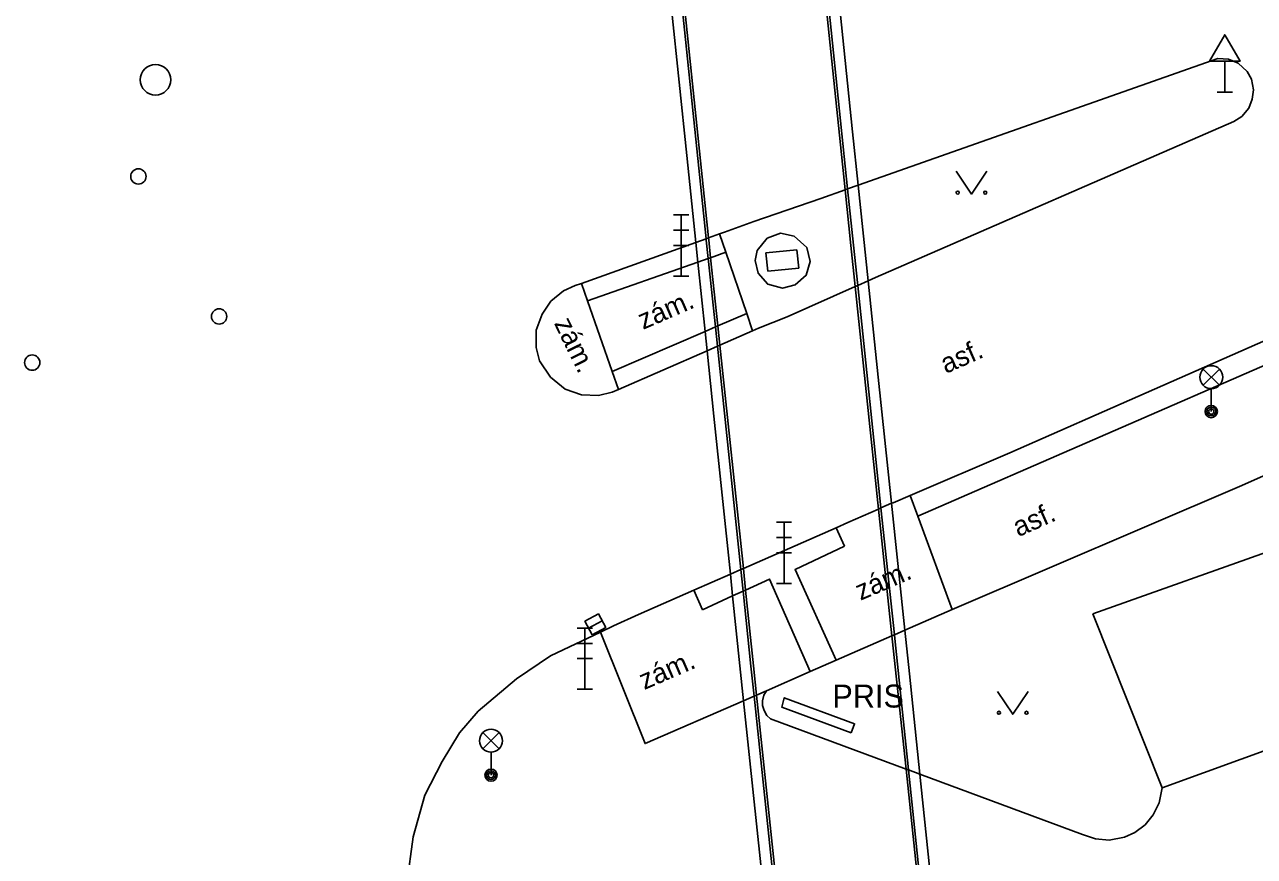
# Model space of a CAD drawing. Extents: x -598341 to -594502, y -1162301 to -1161406.
# Drawn here: x -597773.69 to -597733.48, y -1161818.42 to -1161791.22 of the extents above; entities that cross this region are included whole.
import ezdxf

# ---------------------------------------------------------------- set-up
doc = ezdxf.new("R2010")
doc.units = 0
for name, color, linetype in [('Vrstva 10', 7, 'Continuous'), ('Vrstva 11', 7, 'Continuous'), ('Vrstva 24', 7, 'Continuous'), ('Vrstva 27', 7, 'Continuous'), ('Vrstva 28', 7, 'Continuous'), ('Vrstva 33', 7, 'Continuous'), ('Vrstva 34', 7, 'Continuous'), ('Vrstva 36', 7, 'Continuous'), ('Vrstva 40', 7, 'Continuous'), ('Vrstva 41', 7, 'Continuous'), ('Vrstva 5', 7, 'Continuous'), ('Vrstva 9', 7, 'Continuous')]:
    doc.layers.add(name, color=color, linetype=linetype)

msp = doc.modelspace()

# ---------------------------------------------------------------- linework, layer by layer
at = {"layer": 'Vrstva 10'}
for p, q in [((-597746.44, -1161796.47), (-597734.68, -1161792.32)), ((-597734.15, -1161794.38), (-597745.87, -1161799.49)), ((-597747.66, -1161796.9), (-597746.86, -1161796.62)), ((-597746.86, -1161796.62), (-597746.78, -1161796.59)), ((-597746.78, -1161796.59), (-597746.44, -1161796.47)), ((-597730.43, -1161800.35), (-597741.48, -1161805.22)), ((-597741.48, -1161805.22), (-597744.73, -1161806.61)), ((-597744.73, -1161806.61), (-597745.29, -1161806.85)), ((-597754.86, -1161811.08), (-597756.49, -1161811.86)), ((-597754.44, -1161810.88), (-597754.86, -1161811.08))]:
    msp.add_line(p, q, dxfattribs=at)
for points in [[(-597734.68, -1161792.32), (-597734.33, -1161792.35), (-597734.01, -1161792.48), (-597733.72, -1161792.75), (-597733.58, -1161793), (-597733.51, -1161793.35), (-597733.55, -1161793.65), (-597733.66, -1161793.95), (-597733.89, -1161794.22), (-597734.15, -1161794.38)], [(-597747.66, -1161796.9), (-597749.85, -1161797.65), (-597750.81, -1161798), (-597750.97, -1161798.06)], [(-597751.74, -1161798.34), (-597755.48, -1161799.68)], [(-597751.4, -1161798.22), (-597751.74, -1161798.34)], [(-597751.33, -1161798.19), (-597751.4, -1161798.22)], [(-597750.97, -1161798.06), (-597751.33, -1161798.19)], [(-597746.11, -1161799.6), (-597745.87, -1161799.49)], [(-597754.48, -1161803.24), (-597754.93, -1161803.35), (-597755.48, -1161803.32), (-597756.01, -1161803.14), (-597756.5, -1161802.74), (-597756.85, -1161802.21), (-597756.96, -1161801.77), (-597756.96, -1161801.21), (-597756.77, -1161800.68), (-597756.48, -1161800.26), (-597756.07, -1161799.92), (-597755.69, -1161799.75)], [(-597755.48, -1161799.68), (-597755.69, -1161799.75)], [(-597749.89, -1161801.23), (-597749.69, -1161801.14), (-597748.76, -1161800.77), (-597746.53, -1161799.78)], [(-597746.53, -1161799.78), (-597746.45, -1161799.75)], [(-597746.45, -1161799.75), (-597746.11, -1161799.6)], [(-597750.96, -1161801.7), (-597749.89, -1161801.23)], [(-597754.27, -1161803.15), (-597751.37, -1161801.88)], [(-597751.37, -1161801.88), (-597751.04, -1161801.73)], [(-597751.04, -1161801.73), (-597750.96, -1161801.7)], [(-597754.48, -1161803.24), (-597754.27, -1161803.15)], [(-597747.15, -1161807.67), (-597746.77, -1161807.5), (-597745.77, -1161807.06)], [(-597745.77, -1161807.06), (-597745.69, -1161807.02)], [(-597745.69, -1161807.02), (-597745.35, -1161806.87)], [(-597745.35, -1161806.87), (-597745.29, -1161806.85)], [(-597750.19, -1161809), (-597747.15, -1161807.67)], [(-597751.81, -1161809.71), (-597750.61, -1161809.19)], [(-597750.61, -1161809.19), (-597750.27, -1161809.04)], [(-597750.27, -1161809.04), (-597750.19, -1161809)], [(-597754.44, -1161810.88), (-597753.62, -1161810.51), (-597751.81, -1161809.71)], [(-597760.64, -1161822.54), (-597761.1, -1161820.79), (-597761.19, -1161819.3), (-597760.99, -1161817.78), (-597760.6, -1161816.41), (-597760.04, -1161815.31), (-597759.47, -1161814.38), (-597758.86, -1161813.67), (-597757.61, -1161812.61), (-597756.49, -1161811.86)]]:
    msp.add_lwpolyline(points, dxfattribs=at)
at = {"layer": 'Vrstva 11'}
for p, q in [((-597748.44, -1161798.58), (-597749.45, -1161798.68)), ((-597749.45, -1161798.68), (-597749.39, -1161799.28)), ((-597748.38, -1161799.18), (-597748.44, -1161798.58)), ((-597749.39, -1161799.28), (-597748.38, -1161799.18)), ((-597744.73, -1161806.61), (-597744.48, -1161807.29)), ((-597744.48, -1161807.29), (-597743.36, -1161810.34)), ((-597747.15, -1161807.67), (-597746.88, -1161808.27)), ((-597751.81, -1161809.71), (-597751.53, -1161810.35)), ((-597743.36, -1161810.34), (-597744.91, -1161811.02)), ((-597745.33, -1161811.2), (-597747.16, -1161812)), ((-597745.25, -1161811.17), (-597745.33, -1161811.2)), ((-597744.91, -1161811.02), (-597745.25, -1161811.17)), ((-597747.16, -1161812), (-597748, -1161812.37)), ((-597748, -1161812.37), (-597749.43, -1161813))]:
    msp.add_line(p, q, dxfattribs=at)
for points in [[(-597746.44, -1161796.47), (-597746.62, -1161794.72), (-597747.66, -1161784.64)], [(-597746.78, -1161796.59), (-597748.01, -1161784.72)], [(-597751.74, -1161798.34), (-597752.04, -1161795.5), (-597753.04, -1161785.89)], [(-597751.4, -1161798.22), (-597752.69, -1161785.81)], [(-597743.36, -1161810.34), (-597733.89, -1161806.29), (-597718.92, -1161799.61), (-597712.64, -1161797.05), (-597702.36, -1161793.44), (-597695.71, -1161791.84), (-597669.94, -1161787.58)], [(-597746.45, -1161799.75), (-597746.59, -1161798.43), (-597746.78, -1161796.59)], [(-597746.11, -1161799.6), (-597746.44, -1161796.47)], [(-597751.68, -1161798.98), (-597751.74, -1161798.34)], [(-597751.34, -1161798.86), (-597751.4, -1161798.26), (-597751.4, -1161798.22)], [(-597750.97, -1161798.06), (-597750.76, -1161798.66)], [(-597749.8, -1161798.93), (-597749.74, -1161798.6), (-597749.41, -1161798.2), (-597748.97, -1161798.04), (-597748.53, -1161798.13), (-597748.11, -1161798.51), (-597748, -1161798.96)], [(-597751.26, -1161798.84), (-597750.76, -1161798.66)], [(-597750.76, -1161798.66), (-597750.08, -1161800.66)], [(-597755.28, -1161800.25), (-597751.68, -1161798.98)], [(-597751.68, -1161798.98), (-597751.34, -1161798.86)], [(-597751.44, -1161801.25), (-597751.68, -1161798.98)], [(-597751.34, -1161798.86), (-597751.26, -1161798.84)], [(-597751.1, -1161801.1), (-597751.34, -1161798.86)], [(-597749.8, -1161798.93), (-597749.7, -1161799.34), (-597749.39, -1161799.7), (-597748.91, -1161799.84), (-597748.49, -1161799.73), (-597748.14, -1161799.41), (-597748, -1161798.96)], [(-597755.28, -1161800.25), (-597755.48, -1161799.68)], [(-597745.69, -1161807.02), (-597746.45, -1161799.75)], [(-597745.35, -1161806.87), (-597745.78, -1161802.75), (-597746.11, -1161799.6)], [(-597754.48, -1161802.56), (-597755.28, -1161800.25)], [(-597750.08, -1161800.66), (-597751.02, -1161801.07)], [(-597750.08, -1161800.66), (-597749.89, -1161801.23)], [(-597751.1, -1161801.1), (-597751.44, -1161801.25)], [(-597751.02, -1161801.07), (-597751.1, -1161801.1)], [(-597751.04, -1161801.73), (-597751.1, -1161801.1)], [(-597751.44, -1161801.25), (-597754.48, -1161802.56)], [(-597751.37, -1161801.88), (-597751.44, -1161801.25)], [(-597750.61, -1161809.19), (-597751.15, -1161804.02), (-597751.37, -1161801.88)], [(-597750.27, -1161809.04), (-597751.04, -1161801.73)], [(-597754.27, -1161803.15), (-597754.48, -1161802.56)], [(-597745.25, -1161811.17), (-597745.69, -1161807.02)], [(-597744.91, -1161811.02), (-597745.35, -1161806.87)], [(-597747.16, -1161812), (-597748.5, -1161809.03), (-597746.88, -1161808.27)], [(-597750.54, -1161809.9), (-597750.61, -1161809.19)], [(-597750.2, -1161809.74), (-597750.27, -1161809.04)], [(-597750.12, -1161809.71), (-597749.33, -1161809.35), (-597748, -1161812.37)], [(-597751.53, -1161810.35), (-597750.54, -1161809.9)], [(-597750.54, -1161809.9), (-597750.2, -1161809.74)], [(-597750.18, -1161813.33), (-597750.54, -1161809.9)], [(-597750.2, -1161809.74), (-597750.12, -1161809.71)], [(-597749.84, -1161813.18), (-597749.94, -1161812.2), (-597750.2, -1161809.74)], [(-597750.18, -1161813.33), (-597753.4, -1161814.73), (-597754.86, -1161811.08)], [(-597744.79, -1161815.59), (-597745.24, -1161811.29), (-597745.25, -1161811.17)], [(-597744.42, -1161815.73), (-597744.76, -1161812.45), (-597744.91, -1161811.02)], [(-597749.84, -1161813.18), (-597750.18, -1161813.33)], [(-597749.76, -1161813.14), (-597749.84, -1161813.18)], [(-597748.84, -1161822.65), (-597749.84, -1161813.18)], [(-597749.43, -1161813), (-597749.76, -1161813.14)], [(-597749.3, -1161813.92), (-597749.42, -1161813.81), (-597749.51, -1161813.65), (-597749.56, -1161813.48), (-597749.56, -1161813.33), (-597749.52, -1161813.15), (-597749.43, -1161813)], [(-597749.5, -1161819.83), (-597750, -1161815.08), (-597750.18, -1161813.33)], [(-597749.3, -1161813.92), (-597744.87, -1161815.56)], [(-597744.87, -1161815.56), (-597744.79, -1161815.59)], [(-597744.79, -1161815.59), (-597744.42, -1161815.73)], [(-597743.88, -1161824.28), (-597744.79, -1161815.59)], [(-597743.64, -1161823.16), (-597744.42, -1161815.73)], [(-597744.42, -1161815.73), (-597739.1, -1161817.7)], [(-597739.1, -1161817.7), (-597738.68, -1161817.84), (-597738.23, -1161817.89), (-597737.73, -1161817.79), (-597737.39, -1161817.64), (-597737.05, -1161817.38), (-597736.79, -1161817.06), (-597736.59, -1161816.67), (-597736.5, -1161816.18)]]:
    msp.add_lwpolyline(points, dxfattribs=at)
at = {"layer": 'Vrstva 24'}
msp.add_lwpolyline([(-597746.66, -1161814.38), (-597748.93, -1161813.54), (-597748.85, -1161813.23), (-597746.55, -1161814.08), (-597746.66, -1161814.38)], dxfattribs=at)
at = {"layer": 'Vrstva 27'}
msp.add_line((-597755.25, -1161810.95), (-597754.81, -1161810.71), dxfattribs=at)
msp.add_lwpolyline([(-597755.13, -1161811.169), (-597754.69, -1161810.929), (-597754.93, -1161810.49), (-597755.37, -1161810.73)], close=True, dxfattribs=at)
msp.add_circle((-597769.41, -1161793.02), 0.5, dxfattribs=at)
at = {"layer": 'Vrstva 28'}
for centre in [(-597769.97, -1161796.18), (-597767.33, -1161800.76), (-597773.44, -1161802.27)]:
    msp.add_circle(centre, 0.25, dxfattribs=at)
at = {"layer": 'Vrstva 33'}
for p, q in [((-597752.47, -1161797.44), (-597751.97, -1161797.44)), ((-597752.22, -1161799.44), (-597752.22, -1161797.44)), ((-597752.47, -1161797.94), (-597751.97, -1161797.94)), ((-597752.47, -1161798.44), (-597751.97, -1161798.44)), ((-597752.47, -1161799.44), (-597751.97, -1161799.44)), ((-597735.155, -1161803.01), (-597734.625, -1161802.48)), ((-597735.155, -1161802.48), (-597734.625, -1161803.01)), ((-597734.89, -1161803.12), (-597734.89, -1161803.87)), ((-597749.11, -1161807.49), (-597748.61, -1161807.49)), ((-597748.86, -1161809.49), (-597748.86, -1161807.49)), ((-597749.11, -1161807.99), (-597748.61, -1161807.99)), ((-597749.11, -1161808.49), (-597748.61, -1161808.49)), ((-597749.11, -1161809.49), (-597748.61, -1161809.49)), ((-597755.62, -1161810.95), (-597755.12, -1161810.95)), ((-597755.37, -1161812.95), (-597755.37, -1161810.95)), ((-597755.62, -1161811.45), (-597755.12, -1161811.45)), ((-597755.62, -1161811.95), (-597755.12, -1161811.95)), ((-597755.62, -1161812.95), (-597755.12, -1161812.95)), ((-597758.705, -1161814.9), (-597758.175, -1161814.37)), ((-597758.705, -1161814.37), (-597758.175, -1161814.9)), ((-597758.44, -1161815.01), (-597758.44, -1161815.76))]:
    msp.add_line(p, q, dxfattribs=at)
for centre, radius in [((-597734.89, -1161802.745), 0.375), ((-597734.89, -1161803.87), 0.2), ((-597734.89, -1161803.87), 0.145), ((-597734.89, -1161803.87), 0.0876), ((-597758.44, -1161814.635), 0.375), ((-597758.44, -1161815.76), 0.2), ((-597758.44, -1161815.76), 0.145), ((-597758.44, -1161815.76), 0.0876)]:
    msp.add_circle(centre, radius, dxfattribs=at)
at = {"layer": 'Vrstva 34'}
for p, q in [((-597734.45, -1161792.412), (-597734.45, -1161793.43)), ((-597734.7, -1161793.43), (-597734.2, -1161793.43))]:
    msp.add_line(p, q, dxfattribs=at)
msp.add_lwpolyline([(-597734.95, -1161792.412), (-597733.95, -1161792.412), (-597734.45, -1161791.546)], close=True, dxfattribs=at)
at = {"layer": 'Vrstva 36'}
for points in [[(-597743.23, -1161796.01), (-597742.73, -1161796.76), (-597742.23, -1161796.01)], [(-597741.88, -1161813.02), (-597741.38, -1161813.77), (-597740.88, -1161813.02)]]:
    msp.add_lwpolyline(points, dxfattribs=at)
for centre in [(-597743.18, -1161796.71), (-597742.281, -1161796.71), (-597741.831, -1161813.72), (-597740.931, -1161813.72)]:
    msp.add_circle(centre, 0.05, dxfattribs=at)
at = {"layer": 'Vrstva 5'}
for p, q in [((-597738.76, -1161810.48), (-597715.25, -1161802.15)), ((-597736.5, -1161816.18), (-597738.76, -1161810.48)), ((-597722.31, -1161811), (-597736.5, -1161816.18))]:
    msp.add_line(p, q, dxfattribs=at)
at = {"layer": 'Vrstva 9'}
msp.add_line((-597729.94, -1161800.96), (-597744.48, -1161807.29), dxfattribs=at)
for points in [[(-597746.86, -1161796.62), (-597748.09, -1161784.73)], [(-597751.33, -1161798.19), (-597752.61, -1161785.79)], [(-597746.53, -1161799.78), (-597746.67, -1161798.44), (-597746.86, -1161796.62)], [(-597751.26, -1161798.84), (-597751.32, -1161798.25), (-597751.33, -1161798.19)], [(-597751.02, -1161801.07), (-597751.26, -1161798.84)], [(-597745.77, -1161807.06), (-597746.53, -1161799.78)], [(-597750.96, -1161801.7), (-597751.02, -1161801.07)], [(-597750.19, -1161809), (-597750.96, -1161801.7)], [(-597745.33, -1161811.2), (-597745.77, -1161807.06)], [(-597750.12, -1161809.71), (-597750.19, -1161809)], [(-597749.76, -1161813.14), (-597749.86, -1161812.19), (-597750.12, -1161809.71)], [(-597744.87, -1161815.56), (-597745.32, -1161811.3), (-597745.33, -1161811.2)], [(-597748.76, -1161822.68), (-597749.76, -1161813.14)], [(-597743.96, -1161824.26), (-597744.87, -1161815.56)]]:
    msp.add_lwpolyline(points, dxfattribs=at)

# ---------------------------------------------------------------- texts
at = {"layer": 'Vrstva 40'}
for s, rotation, p in [('zám.', 23.3405, (-597753.47, -1161801.2)), ('zám.', 296.1867, (-597756.39, -1161800.98)), ('asf.', 23.6788, (-597743.57, -1161802.64)), ('asf.', 23.8872, (-597741.2, -1161807.98)), ('zám.', 23.3405, (-597746.36, -1161810.06)), ('zám.', 23.3405, (-597753.43, -1161812.98))]:
    msp.add_text(s, height=0.65, rotation=rotation, dxfattribs=at).set_placement(p)
at = {"layer": 'Vrstva 41'}
msp.add_text('PRIS', height=0.75, dxfattribs=at).set_placement((-597747.28, -1161813.55))

doc.saveas('drawing.dxf')
